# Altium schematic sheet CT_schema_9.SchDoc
size 147 x 119 mm
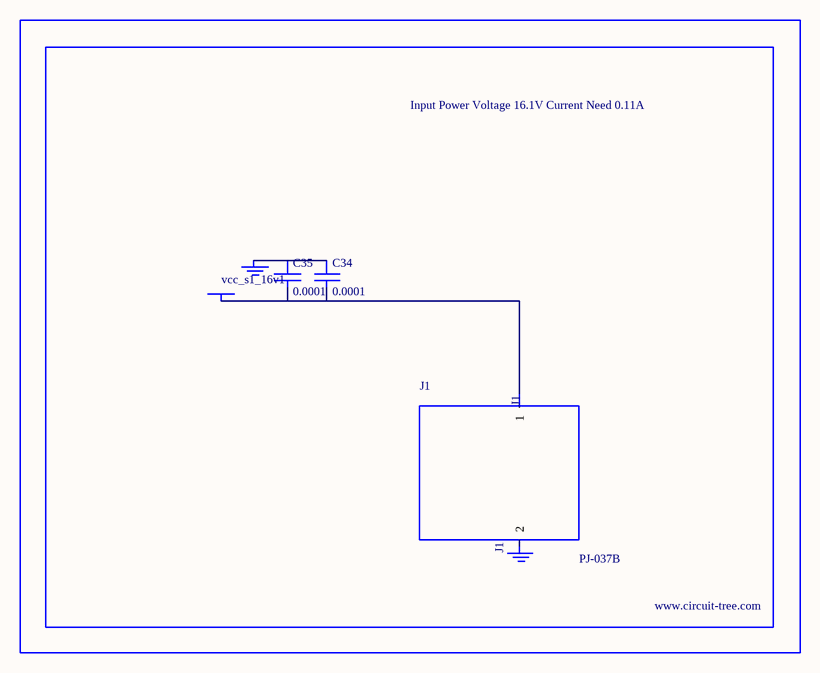
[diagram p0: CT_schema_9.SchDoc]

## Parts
BORDER8  (no value)
C34  0.0001  [EXV-9H]
C35  0.0001  [EXV-9H]
GND_INSTANCE_8_0  (no value)
GND_INSTANCE_8_1  (no value)
J1  PJ-037B  [PJ-037B_PACKAGE]
POWER_INSTANCE_8_0  vcc_s1_16v1

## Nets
NetC34_1: C34.1 C35.1 GND_INSTANCE_8_0.0(GND)
NetC34_2: C34.2 C35.2 J1.1 POWER_INSTANCE_8_0.0(PWR)

Not connected (* = marked no-connect by the designer): GND_INSTANCE_8_1 0(GND); J1 2

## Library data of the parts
BORDER8 = BORDER_PAGE8
C34 C35 = EDK107M035A9HAA
GND_INSTANCE_8_0 GND_INSTANCE_8_1 = GND
POWER_INSTANCE_8_0 = PWR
